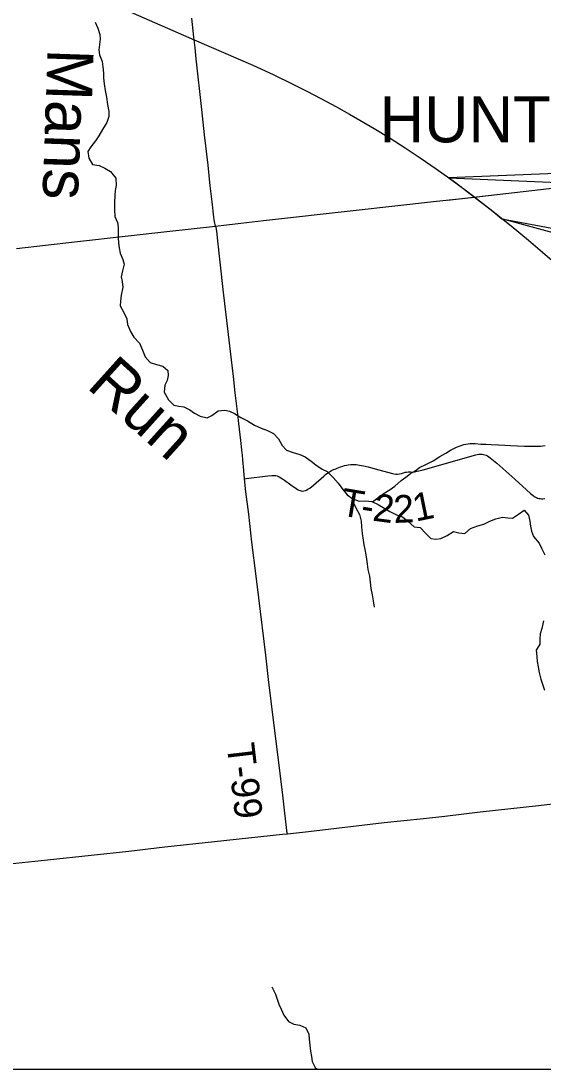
# Model space of a CAD drawing. Extents: x -5.9 to 34, y 0 to 22.
# Drawn here: x 3.776 to 5.923, y 14 to 18.309 of the extents above; entities that cross this region are included whole.
import ezdxf

# ---------------------------------------------------------------- set-up
doc = ezdxf.new("R2010")
doc.units = 0
for name, color, linetype in [('GM_X_Corporation_Text', 7, 'Continuous'), ('GM_X_County_Road', 7, 'Continuous'), ('GM_X_Minor_River', 7, 'Continuous'), ('GM_X_Minor_River_Text', 7, 'Continuous'), ('GM_X_State_Route', 7, 'Continuous'), ('GM_X_Township_Road', 7, 'Continuous'), ('GM_X_Township_Road_Text', 7, 'Continuous'), ('GM_X_US_Route', 7, 'Continuous'), ('SH_Data', 7, 'Continuous'), ('SH_Text', 7, 'Continuous')]:
    doc.layers.add(name, color=color, linetype=linetype)

msp = doc.modelspace()

# ---------------------------------------------------------------- linework, layer by layer
at = {"layer": 'GM_X_County_Road'}
msp.add_lwpolyline([(3.7025, 14.8404), (3.8842, 14.8597), (4.0646, 14.8794), (4.219, 14.896), (4.3672, 14.913), (4.5723, 14.935), (4.8516, 14.965), (4.8716, 14.9672), (4.9578, 14.9769), (5.2702, 15.0132), (5.4308, 15.0303), (5.5185, 15.0403), (5.6642, 15.0568), (5.9038, 15.0835), (6.0323, 15.0983)], dxfattribs=at)
at = {"layer": 'GM_X_Minor_River'}
for points in [[(4.0808, 18.3037), (4.0917, 18.2792), (4.1004, 18.2533), (4.1008, 18.2335), (4.0982, 18.2123), (4.0956, 18.1904), (4.0982, 18.1698), (4.1091, 18.1423), (4.1118, 18.121), (4.1144, 18.0937), (4.1148, 18.0747), (4.1175, 18.0503), (4.1216, 18.0229), (4.1272, 17.9955), (4.132, 17.9651), (4.1368, 17.9369), (4.1365, 17.9164), (4.1285, 17.8915), (4.1106, 17.8622), (4.0958, 17.8374), (4.0826, 17.8164), (4.0633, 17.7917), (4.0508, 17.7722), (4.0549, 17.7448), (4.0697, 17.7187), (4.0976, 17.7145), (4.1209, 17.7042), (4.1434, 17.6901), (4.1656, 17.6624), (4.1666, 17.6321), (4.1633, 17.6124), (4.1622, 17.5934), (4.1609, 17.5616), (4.1597, 17.532), (4.1623, 17.5054), (4.1725, 17.4802), (4.1759, 17.4604), (4.1756, 17.4399), (4.176, 17.4194), (4.1772, 17.3958), (4.1799, 17.376), (4.184, 17.354), (4.195, 17.328), (4.2007, 17.3089), (4.1935, 17.2817), (4.1878, 17.2575), (4.192, 17.2377), (4.1939, 17.2141), (4.1881, 17.1823), (4.1854, 17.1573), (4.1835, 17.1376), (4.199, 17.1108), (4.2114, 17.0848), (4.2133, 17.0612), (4.2257, 17.0329), (4.2397, 17.0084), (4.2628, 16.9837), (4.276, 16.9561), (4.2861, 16.9286), (4.3069, 16.9055), (4.3333, 16.896), (4.3589, 16.8902), (4.379, 16.8716), (4.3817, 16.8519), (4.3776, 16.8314), (4.3667, 16.8111), (4.364, 16.7823), (4.3831, 16.7509), (4.4047, 16.73), (4.4243, 16.7259), (4.4455, 16.7225), (4.4695, 16.7099), (4.489, 16.6967), (4.513, 16.6841), (4.5416, 16.6768), (4.5607, 16.6864), (4.5867, 16.7057), (4.614, 16.7082), (4.6336, 16.7041), (4.6539, 16.6947), (4.6794, 16.6791), (4.7079, 16.6649), (4.7364, 16.6477), (4.7642, 16.6351), (4.789, 16.6248), (4.8138, 16.613), (4.8354, 16.5914), (4.8493, 16.5638), (4.8679, 16.5438), (4.8958, 16.535), (4.9229, 16.5269), (4.9439, 16.5174), (4.9686, 16.4996), (4.9888, 16.484), (5.015, 16.4669), (5.0353, 16.4567), (5.0599, 16.432), (5.0799, 16.4089), (5.0992, 16.382), (5.117, 16.3612), (5.1409, 16.3448)], [(5.2209, 16.3319), (5.2378, 16.3447), (5.2692, 16.367), (5.2944, 16.3832), (5.3136, 16.3966), (5.3389, 16.4197), (5.3581, 16.433), (5.3772, 16.4479), (5.3964, 16.4597), (5.4155, 16.473), (5.4437, 16.487), (5.4704, 16.501), (5.498, 16.5187), (5.5232, 16.5319), (5.5423, 16.5445), (5.5667, 16.5563), (5.5972, 16.5679), (5.623, 16.5712), (5.6434, 16.5717), (5.6668, 16.5697), (5.6873, 16.5687), (5.7099, 16.5675), (5.7394, 16.5662), (5.7659, 16.5643), (5.7893, 16.5631), (5.8181, 16.5619), (5.8461, 16.5607), (5.8657, 16.5603), (5.8877, 16.5607), (5.9119, 16.5611), (5.9316, 16.563)], [(5.138, 16.3469), (5.1429, 16.3273), (5.1532, 16.3067), (5.1679, 16.2798), (5.175, 16.2524), (5.1761, 16.2288), (5.1795, 16.2015), (5.1828, 16.1748), (5.1863, 16.155), (5.1898, 16.136), (5.1939, 16.1147), (5.1967, 16.0957), (5.1994, 16.0759), (5.2028, 16.0538), (5.2092, 16.0264), (5.2125, 16.0013), (5.2151, 15.9754), (5.22, 15.9503), (5.2249, 15.9244), (5.229, 15.8985)], [(5.1409, 16.3448), (5.1673, 16.3345), (5.1945, 16.3363), (5.2187, 16.3329), (5.2442, 16.3211), (5.272, 16.3039), (5.293, 16.2922), (5.32, 16.2788), (5.3456, 16.27), (5.3665, 16.253), (5.3933, 16.229), (5.4175, 16.227), (5.4391, 16.2032), (5.4614, 16.1808), (5.4818, 16.1789), (5.5023, 16.1816), (5.529, 16.194), (5.5543, 16.2103), (5.5761, 16.2039), (5.6018, 16.2012), (5.6248, 16.222), (5.6553, 16.2329), (5.6796, 16.2401), (5.7048, 16.2526), (5.7292, 16.262), (5.7558, 16.2684), (5.7777, 16.2665), (5.7973, 16.2654), (5.8226, 16.2817), (5.8455, 16.2973), (5.8626, 16.2765), (5.8683, 16.2521), (5.8717, 16.2323), (5.8759, 16.211), (5.8839, 16.1888), (5.9069, 16.1619), (5.9172, 16.1412), (5.9303, 16.1137)], [(5.9244, 15.8428), (5.9178, 15.811), (5.9114, 15.7898), (5.9095, 15.7671), (5.9099, 15.7466), (5.8952, 15.7226), (5.897, 15.696), (5.8982, 15.6762), (5.9031, 15.6541), (5.9073, 15.6298), (5.9144, 15.6023), (5.9223, 15.5779), (5.9296, 15.558)], [(4.8076, 14.3374), (4.8222, 14.3076), (4.8295, 14.2877), (4.8367, 14.2664), (4.8454, 14.2465), (4.8571, 14.222), (4.8756, 14.1951), (4.8981, 14.1849), (4.9231, 14.1807), (4.9478, 14.1689), (4.9603, 14.1436), (4.9607, 14.1224), (4.9641, 14.0988), (4.9667, 14.0737), (4.9701, 14.0516), (4.9736, 14.0311), (4.986, 14.0058), (4.9934, 14)]]:
    msp.add_lwpolyline(points, dxfattribs=at)
at = {"layer": 'GM_X_State_Route'}
msp.add_lwpolyline([(3.7566, 17.3738), (3.9962, 17.401), (4.2161, 17.4254), (4.3756, 17.4435), (4.5763, 17.466), (4.6794, 17.478), (4.773, 17.4892), (5.1549, 17.5316), (5.4721, 17.5669), (5.6415, 17.5845), (5.6627, 17.5867), (5.8415, 17.608), (6.1033, 17.6378), (6.3787, 17.669), (6.5303, 17.6858), (6.7208, 17.707), (6.7907, 17.7148)], dxfattribs=at)
at = {"layer": 'GM_X_Township_Road'}
for points in [[(4.8716, 14.9672), (4.8712, 14.9702), (4.8606, 15.0525), (4.8521, 15.1253), (4.8431, 15.2043), (4.8053, 15.5127), (4.7939, 15.6014), (4.7821, 15.7014), (4.7535, 15.937), (4.7424, 16.0257), (4.7258, 16.1664), (4.7124, 16.2812), (4.7012, 16.3737), (4.6954, 16.4269), (4.6917, 16.4602), (4.6879, 16.5047), (4.6862, 16.5238), (4.6838, 16.5464), (4.6797, 16.5845), (4.6715, 16.654), (4.667, 16.6929), (4.6572, 16.7806), (4.6499, 16.8473), (4.6413, 16.9163), (4.6079, 17.2051), (4.5837, 17.4175), (4.5809, 17.4455), (4.5805, 17.4493), (4.5798, 17.4538), (4.579, 17.4575), (4.5782, 17.4603), (4.5763, 17.466), (4.5747, 17.4718), (4.5732, 17.4781), (4.5719, 17.4846), (4.5706, 17.4918), (4.5691, 17.5027), (4.5617, 17.5657), (4.5544, 17.6311), (4.5451, 17.7156), (4.5309, 17.8404), (4.5199, 17.9443), (4.4968, 18.1532), (4.4922, 18.1983), (4.4884, 18.2318), (4.4872, 18.2425), (4.4784, 18.3199)], [(4.6954, 16.4269), (4.7018, 16.4276), (4.7908, 16.4384), (4.8072, 16.44), (4.8169, 16.4404), (4.824, 16.4397), (4.8296, 16.4382), (4.8347, 16.4364), (4.8383, 16.4346), (4.845, 16.4309), (4.8518, 16.4267), (4.8599, 16.4212), (4.8862, 16.4021), (4.9077, 16.3868), (4.9133, 16.3829), (4.9185, 16.3802), (4.9235, 16.3783), (4.9284, 16.3771), (4.9338, 16.3765), (4.9394, 16.3766), (4.9453, 16.3781), (4.9503, 16.3802), (4.9555, 16.3834), (4.9631, 16.3885), (4.9784, 16.4003), (5.0211, 16.438), (5.0288, 16.4442), (5.0377, 16.4508), (5.0453, 16.4559), (5.0535, 16.4605), (5.0616, 16.4643), (5.0703, 16.4679), (5.0767, 16.4706), (5.0833, 16.4732), (5.0905, 16.4758), (5.099, 16.4791), (5.1061, 16.4815), (5.1144, 16.4834), (5.1216, 16.4846), (5.133, 16.4852), (5.1428, 16.4854), (5.1549, 16.4848), (5.1674, 16.4829), (5.1839, 16.48), (5.2037, 16.4753), (5.2481, 16.4633), (5.3034, 16.4479), (5.3093, 16.4467), (5.3174, 16.4459), (5.3245, 16.4457), (5.3325, 16.4467), (5.3411, 16.449), (5.3496, 16.4515), (5.356, 16.4535), (5.3615, 16.4546), (5.3689, 16.4551), (5.3784, 16.4547), (5.3837, 16.4546), (5.3892, 16.4548), (5.3943, 16.4555), (5.3995, 16.4565), (5.4297, 16.4642), (5.6468, 16.525), (5.6525, 16.5265), (5.6592, 16.5274), (5.6651, 16.5279), (5.6722, 16.5276), (5.6784, 16.5266), (5.6842, 16.5253), (5.6895, 16.5232), (5.6942, 16.5209), (5.6998, 16.5176), (5.706, 16.5133), (5.7328, 16.4912), (5.8073, 16.4255), (5.8718, 16.366), (5.8765, 16.362), (5.8818, 16.3577), (5.8855, 16.355), (5.8891, 16.3528), (5.8922, 16.351), (5.8958, 16.3492), (5.9007, 16.3474), (5.9061, 16.3461), (5.9108, 16.3452), (5.9173, 16.3448), (5.9223, 16.3447), (5.9298, 16.3452)]]:
    msp.add_lwpolyline(points, dxfattribs=at)
at = {"layer": 'GM_X_US_Route'}
for points in [[(2, 19.3167), (2.2817, 19.1938), (2.4324, 19.1281), (2.664, 19.0275), (3.1289, 18.8249), (3.5288, 18.6508), (3.8257, 18.5209), (4.2154, 18.3506), (4.4884, 18.2318), (4.7297, 18.1268), (4.8133, 18.0883), (4.8942, 18.0495), (4.9519, 18.0205), (5.0087, 17.9907), (5.074, 17.9558), (5.1267, 17.9263), (5.229, 17.8668), (5.2943, 17.8268), (5.3561, 17.7876), (5.4175, 17.7463), (5.483, 17.701), (5.5631, 17.6446), (5.6415, 17.5845)], [(5.6415, 17.5845), (5.7045, 17.5362), (5.7919, 17.4669), (5.8637, 17.4078), (5.9211, 17.3584), (5.9702, 17.3153), (6.027, 17.2622), (6.0827, 17.2079), (6.1425, 17.1497), (6.3662, 16.9237), (6.587, 16.7006), (6.7781, 16.5066), (6.8546, 16.4296), (6.9082, 16.3759), (6.9277, 16.356)]]:
    msp.add_lwpolyline(points, dxfattribs=at)
at = {"layer": 'SH_Data'}
for p, q in [((5.5294, 17.5729), (5.7332, 17.5951)), ((2, 14), (9, 14))]:
    msp.add_line(p, q, dxfattribs=at)
for points in [[(5.5354, 17.6641), (5.6029, 17.6141), (5.6421, 17.584)], [(5.6421, 17.584), (5.6737, 17.5598), (5.7173, 17.5252), (5.7532, 17.4957)]]:
    msp.add_lwpolyline(points, dxfattribs=at)
at = {"layer": 'SH_Text'}
for points in [[(9.6717, 17.8317), (5.5354, 17.6641), (9.6717, 17.4879)], [(9.6586, 16.4313), (5.7532, 17.4957), (9.6586, 16.7683)]]:
    msp.add_lwpolyline(points, close=True, dxfattribs=at)

# ---------------------------------------------------------------- texts
at = {"layer": 'GM_X_Corporation_Text'}
msp.add_text('HUNTSVILLE', height=0.18939, rotation=0, dxfattribs=at).set_placement((5.2509, 17.81))
at = {"layer": 'GM_X_Minor_River_Text'}
for s, height, rotation, p in [('Mans', 0.18948, 268.0452, (3.8854, 18.1964)), ('Run', 0.1895, 318.022, (4.0413, 16.8038))]:
    msp.add_text(s, height=height, rotation=rotation, dxfattribs=at).set_placement(p)
at = {"layer": 'GM_X_Township_Road_Text'}
for s, height, rotation, p in [('T', 0.1136, 350.5546, (5.0849, 16.2772)), ('2', 0.1136, 352.3684, (5.2187, 16.2551)), ('2', 0.1136, 2.495, (5.3099, 16.2448)), ('1', 0.1136, 11.5594, (5.3993, 16.2503)), ('-', 0.1136, 350.7189, (5.1691, 16.2632)), ('T-99', 0.11364, 276.7309, (4.6215, 15.3336))]:
    msp.add_text(s, height=height, rotation=rotation, dxfattribs=at).set_placement(p)

doc.saveas('drawing.dxf')
